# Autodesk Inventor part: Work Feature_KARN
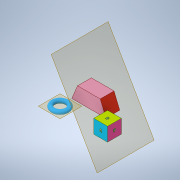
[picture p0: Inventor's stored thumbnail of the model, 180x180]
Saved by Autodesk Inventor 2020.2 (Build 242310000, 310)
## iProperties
Created: 2018-06
Part Number: Work Feature_KARN
Material: Generic
Document SubType Name: Modeling
Designer: Power User
Density: 1 g/cm^3
Appearance: Light Red
Author: Power User
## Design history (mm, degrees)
sketch "Sketch1"
  geometry: L1 (0, 0)-(50, 0); L2 (50, 0)-(50, -50); L3 (50, -50)-(0, -50); L4 (0, -50)-(0, 0); 1 further point
  constraints: 8 end point, 2 parallel, 1 coincident, 1 horizontal, 1 perpendicular
  dimensions: "d0" = 50 distance of L1.end L2.end; "d1" = 50 distance of L2.end L3.end; "d53" = 0 distance from line of point (0, 0) L4
extrude "Extrusion1" new body sketch "Sketch1" distance "d2" = 50; taper "d3" = 0 deg
workplane "Work Plane1"
sketch "Sketch2"
  geometry: L1 (0, 50)-(50, 50) reference; L2 (50, 0)-(50, 50) reference; C1 r 20 at (-30, 25); 3 further points
  constraints: 2 midpoint, 1 centre point, 1 horizontal alignment
  dimensions: "d5" = 40 diameter of C1; "d54" = 30 horizontal distance of C1.centre point (0, 0)
extrude "Extrusion2" new body sketch "Sketch2" distance "d6" = 50; taper "d7" = 0 deg
sketch "Sketch3"
  geometry: L1 (-172.16, 49.98)-(-172.16, 11.482); C1 r 7.5 at (-197.16, 26.587); 1 further point
  constraints: 2 end point, 1 centre point, 1 vertical
  dimensions: "d8" = 15 diameter of C1; "d9" = 50 diameter of C1.centre L1
revolve "Revolution1" sketch "Sketch3" stored, may be unused: angle "d10" = 90 deg
workplane "Work Plane2"
sketch "Sketch4"
  geometry: L1 (-98.807, 58.325)-(-98.807, 8.325); A1 r 25 centre (-98.807, 33.325) between (-98.807, 58.325) and (-98.807, 8.325); 1 further point
  constraints: 2 end point, 2 point on circle, 1 centre point, 1 vertical
  dimensions: "d12" = 50 diameter of A1
revolve "Revolution2" sketch "Sketch4" stored, may be unused: angle "d13" = 90 deg
workplane "Work Plane3"
sketch "Sketch5"
  geometry: L1 (-192.037, 9.98)-(-171.326, 59.98); L2 (-171.326, 59.98)-(-89.041, 59.98); L3 (-89.041, 59.98)-(-68.33, 9.98); L4 (-68.33, 9.98)-(-192.037, 9.98); L5 (-130.184, 59.98)-(-130.184, 9.98); 1 further point
  constraints: 10 end point, 2 midpoint, 1 horizontal, 1 parallel, 1 perpendicular, 1 other
  dimensions: "d15" = 50 distance between parallel lines of L4 L2; "d16" = 45 deg angle of L3 L1
extrude "Extrusion3" new body sketch "Sketch5" stored distance "d17" = 50; taper "d18" = 0 deg
sketch "Sketch6"
  geometry: L1 (15, 35)-(35, 35); L2 (35, 35)-(35, 15); L3 (35, 15)-(15, 15); L4 (15, 15)-(15, 35); L5 (0, 50)-(50, 50) reference; L6 (0, 0)-(0, 50) reference; 5 further points
  constraints: 4 midpoint, 1 horizontal alignment, 1 vertical alignment, 2 other
  dimensions: "d19" = 20 distance of L1.start L1.end; "d20" = 20 distance of L1.end L2.end
emboss "Emboss1" sketch "Sketch6" dims "d0" = 50, "d1" = 50, "d21" = 0.2, "d22" = 0, "d53" = 0
sketch "Sketch7"
  geometry: L1 (-35, 35)-(-15, 35); L2 (-15, 35)-(-15, 15); L3 (-15, 15)-(-35, 15); L4 (-35, 15)-(-35, 35); L5 (0, 50)-(-50, 50) reference; L6 (-50, 50)-(-50, 0) reference; 5 further points
  constraints: 4 midpoint, 1 horizontal alignment, 1 vertical alignment, 2 other
  dimensions: "d23" = 20 distance of L1.start L1.end; "d24" = 20 distance of L3.end L1.start
emboss "Emboss2" sketch "Sketch7" dims "d0" = 50, "d1" = 50, "d25" = 0.2, "d26" = 0, "d53" = 0
sketch "Sketch8"
  geometry: L1 (15, 35)-(35, 35); L2 (35, 35)-(35, 15); L3 (35, 15)-(15, 15); L4 (15, 15)-(15, 35); L5 (0, 0)-(0, 50) reference; L6 (0, 50)-(50, 50) reference; 4 further points
  constraints: 4 midpoint, 1 horizontal alignment, 1 vertical alignment, 2 other
  dimensions: "d27" = 20 distance of L1.start L1.end; "d28" = 20 distance of L3.end L1.start
emboss "Emboss3" sketch "Sketch8" dims "d0" = 50, "d1" = 50, "d29" = 0.2, "d30" = 0, "d53" = 0
sketch "Sketch9"
  geometry: L1 (-11.219, -35.018)-(-35.694, -35.018); L2 (-35.694, -35.018)-(-35.694, -14.982); L3 (-35.694, -14.982)-(-11.219, -14.982); L4 (-11.219, -14.982)-(-11.219, -35.018); L5 (0, -50)-(0, 0) reference; 4 further points
  constraints: 3 midpoint, 1 horizontal alignment, 1 vertical alignment, 2 other
emboss "Emboss4" sketch "Sketch9" dims "d0" = 50, "d1" = 50, "d31" = 0.2, "d32" = 0, "d53" = 0
sketch "Sketch10"
  geometry: L1 (15, 35)-(35, 35); L2 (35, 35)-(35, 15); L3 (35, 15)-(15, 15); L4 (15, 15)-(15, 35); L5 (0, 50)-(50, 50) reference; L6 (0, 0)-(0, 50) reference; 5 further points
  constraints: 4 midpoint, 1 horizontal alignment, 1 vertical alignment, 2 other
  dimensions: "d33" = 20 distance of L1.start L1.end; "d34" = 20 distance of L3.end L1.start
emboss "Emboss5" sketch "Sketch10" dims "d0" = 50, "d1" = 50, "d35" = 0.2, "d36" = 0, "d53" = 0
sketch "Sketch11"
  geometry: L1 (15, 35)-(35, 35); L2 (35, 35)-(35, 15); L3 (35, 15)-(15, 15); L4 (15, 15)-(15, 35); L5 (0, 0)-(0, 50) reference; L6 (0, 50)-(50, 50) reference; 4 further points
  constraints: 4 midpoint, 1 horizontal alignment, 1 vertical alignment, 2 other
  dimensions: "d37" = 20 distance of L1.start L1.end; "d38" = 20 distance of L1.end L2.end
emboss "Emboss6" sketch "Sketch11" dims "d0" = 50, "d1" = 50, "d39" = 0.2, "d40" = 0, "d53" = 0
sketch "Sketch12"
  geometry: L1 (118.439, 97.246)-(43.439, 97.246); L2 (43.439, 97.246)-(43.439, 172.246); L3 (43.439, 172.246)-(58.439, 172.246); L4 (58.439, 172.246)-(58.439, 112.246); L5 (58.439, 112.246)-(118.439, 112.246); L6 (118.439, 112.246)-(118.439, 97.246); 1 further point
  constraints: 12 end point, 4 perpendicular, 1 horizontal, 1 vertical
  dimensions: "d41" = 75 distance of L1.start L1.end; "d42" = 75 distance of L1.end L2.end (= d41); "d43" = 15 distance of L5.end L1.start; "d44" = 15 distance of L2.end L3.end (= d43)
extrude "Extrusion4" new body sketch "Sketch12" stored distance "d45" = 100; taper "d46" = 0 deg
sketch "Sketch13"
  geometry: L1 (97.246, 118.439)-(97.246, 43.439) reference; L2 (97.246, 43.439)-(172.246, 43.439) reference; L3 (172.246, 43.439)-(97.246, 43.439) reference; L4 (172.246, 118.439)-(97.246, 118.439); L5 (97.246, 118.439)-(97.246, 43.439); L6 (97.246, 43.439)-(172.246, 43.439); L7 (172.246, 43.439)-(172.246, 118.439); L8 (172.246, 118.439)-(97.246, 43.439); L9 (97.246, 118.439)-(172.246, 43.439); 2 further points
  constraints: 12 end point, 2 equal length, 2 midpoint, 2 parallel, 1 horizontal, 1 perpendicular
extrude "Extrusion5" join sketch "Sketch13" distance "d47" = 15; taper "d48" = 0 deg
feature "Move Body1"
workplane "Work Plane4"
workplane "Work Plane5"
workplane "Work Plane6"
workplane "Work Plane7"
workplane "Work Plane8"
workplane "Work Plane9"
workplane "Work Plane10"
node "Cube"
node "Cylinder"
node "Ring"
node "Sphere"
node "Trapezoid"
node "Solid"
other parameters: "d14" = -87.5, "d57" = -30 deg
